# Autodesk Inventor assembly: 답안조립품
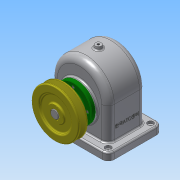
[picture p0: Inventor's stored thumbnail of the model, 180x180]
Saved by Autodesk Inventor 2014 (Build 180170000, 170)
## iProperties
Created: 2016-10
Part Number: 답안조립품
Document SubType Name: Assembly
Designer: user
Author: user
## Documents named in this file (15)
- C:\Users\user\Desktop\461008V1023\답안조립품.iam
- C:\Users\user\Desktop\461008V1023\1-본체.ipt
- C:\Users\user\Desktop\461008V1023\뒤커버.ipt
- C:\Users\user\Desktop\461008V1023\앞커버.ipt
- C:\Users\user\Desktop\461008V1023\베어링 6203.ipt
- C:\Users\user\Desktop\461008V1023\볼트 M3 x 8.ipt
- C:\Users\user\Desktop\461008V1023\볼트 M3 x 10.ipt
- C:\Users\user\Desktop\461008V1023\오일씰 28 40 8.ipt
- C:\Users\user\Desktop\461008V1023\축.ipt
- C:\Users\user\Desktop\461008V1023\키 - 6 x 6 x 22.ipt
- C:\Users\user\Desktop\461008V1023\스퍼기어.ipt
- C:\Users\user\Desktop\461008V1023\V-벨트풀리.ipt
- C:\Users\user\Desktop\461008V1023\키 - 5 x 5 x 18.ipt
- C:\Users\user\Desktop\461008V1023\멈춤나사 - M4x10.ipt
- C:\Users\user\Desktop\461008V1023\부시.ipt
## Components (10 placed, 4 different names)
1. 1-본체:1 — Mate:1, Mate:2, Mate:3, Mate:4, Mate:5, Mate:6
2. V-벨트풀리:1 — Mate:25, Mate:29, Mate:30, Mate:31
3. ISO 4762 M3 x 8:1 — Mate:11, Mate:12
4. ISO 4762 M3 x 8:2
5. ISO 4762 M3 x 8:3
6. ISO 4762 M3 x 8:4
7. ISO 4762 M3 x 10:1 — Mate:13, Mate:14
8. ISO 4762 M3 x 10:2
9. ISO 4762 M3 x 10:3
10. ISO 4762 M3 x 10:4
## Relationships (14: Mate 14)
- Mate:1: 1-본체:1
- Mate:2: 1-본체:1
- Mate:3: 1-본체:1
- Mate:4: 1-본체:1
- Mate:5: 1-본체:1
- Mate:6: 1-본체:1
- Mate:11: ISO 4762 M3 x 8:1
- Mate:12: ISO 4762 M3 x 8:1
- Mate:13: ISO 4762 M3 x 10:1
- Mate:14: ISO 4762 M3 x 10:1
- Mate:25: V-벨트풀리:1
- Mate:29: V-벨트풀리:1
- Mate:30: V-벨트풀리:1
- Mate:31: V-벨트풀리:1
